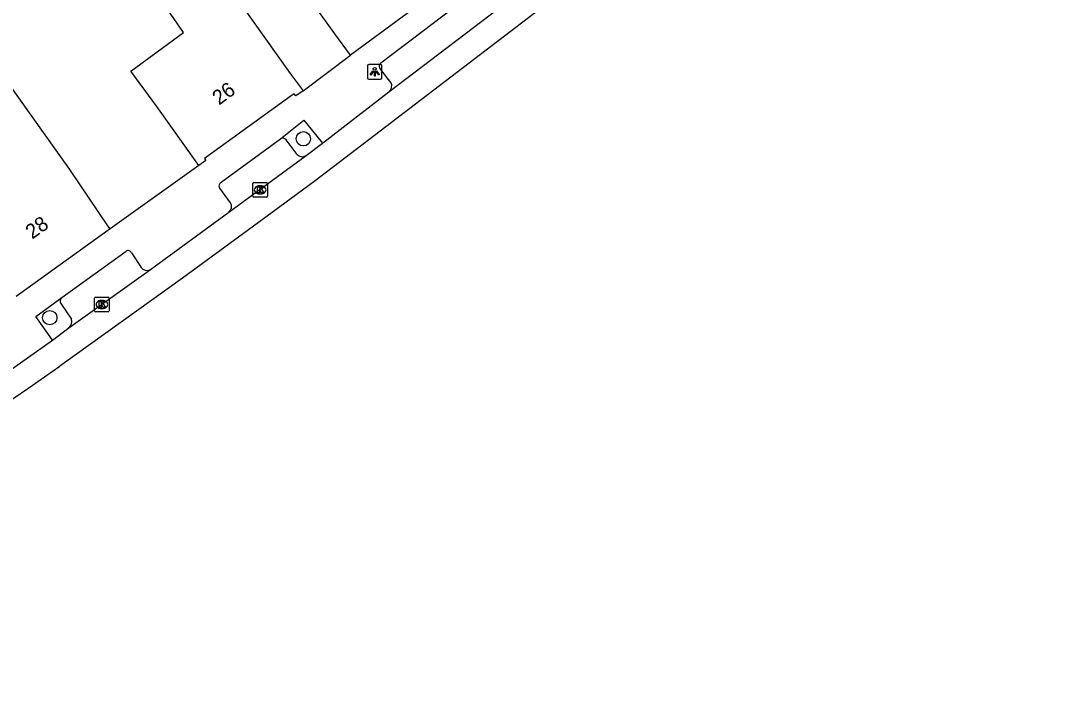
# Model space of a CAD drawing. Extents: x 159377 to 159983, y 382996 to 383595.
# Drawn here: x 159877.4 to 159949, y 383190.3 to 383236.9 of the extents above; entities that cross this region are included whole.
import ezdxf

# ---------------------------------------------------------------- set-up
doc = ezdxf.new("R2010")
doc.units = 0
for name, color, linetype in [('IMGEO_Boom', 7, 'Continuous'), ('IMGEO_Kolk', 7, 'Continuous'), ('IMGEO_Lichtpunt', 7, 'Continuous'), ('IMGEO_Pand', 7, 'Continuous'), ('IMGEO_Pand_nummerreeks', 7, 'Continuous'), ('IMGEO_Parkeervlak_open', 7, 'Continuous'), ('IMGEO_Rijbaan_lokaal_gesloten', 7, 'Continuous'), ('IMGEO_Voetpad_open', 7, 'Continuous')]:
    doc.layers.add(name, color=color, linetype=linetype)

msp = doc.modelspace()

# ---------------------------------------------------------------- linework, layer by layer
at = {"layer": 'IMGEO_Boom'}
for centre in [(159896.695, 383228.822), (159879.406, 383216.62)]:
    msp.add_circle(centre, 0.489, dxfattribs=at)
at = {"layer": 'IMGEO_Kolk'}
for p, q in [((159893.249, 383224.914), (159893.249, 383225.766)), ((159893.324, 383225.84), (159894.176, 383225.84)), ((159894.25, 383225.766), (159894.25, 383224.914)), ((159893.76, 383225.06), (159893.735, 383225.06)), ((159893.737, 383225.62), (159893.762, 383225.62)), ((159894.176, 383224.84), (159893.324, 383224.84)), ((159882.46, 383217.094), (159882.46, 383217.946)), ((159882.535, 383218.02), (159883.387, 383218.02)), ((159883.461, 383217.946), (159883.461, 383217.094)), ((159882.971, 383217.24), (159882.946, 383217.24)), ((159882.948, 383217.8), (159882.973, 383217.8)), ((159883.387, 383217.02), (159882.535, 383217.02))]:
    msp.add_line(p, q, dxfattribs=at)
for points in [[(159893.249, 383224.914), (159893.249, 383225.766)], [(159893.324, 383225.84), (159894.176, 383225.84)], [(159894.25, 383225.766), (159894.25, 383224.914)], [(159893.57, 383225.54), (159893.693, 383225.54), (159893.693, 383225.389), (159893.823, 383225.54), (159893.987, 383225.54), (159893.841, 383225.389), (159893.994, 383225.14), (159893.842, 383225.14), (159893.757, 383225.304), (159893.693, 383225.237), (159893.693, 383225.14), (159893.57, 383225.14), (159893.57, 383225.54)], [(159894.176, 383224.84), (159893.324, 383224.84)], [(159882.46, 383217.094), (159882.46, 383217.946)], [(159882.535, 383218.02), (159883.387, 383218.02)], [(159883.461, 383217.946), (159883.461, 383217.094)], [(159882.781, 383217.72), (159882.904, 383217.72), (159882.904, 383217.569), (159883.034, 383217.72), (159883.198, 383217.72), (159883.052, 383217.569), (159883.205, 383217.32), (159883.053, 383217.32), (159882.968, 383217.484), (159882.904, 383217.417), (159882.904, 383217.32), (159882.781, 383217.32), (159882.781, 383217.72)], [(159883.387, 383217.02), (159882.535, 383217.02)]]:
    msp.add_lwpolyline(points, dxfattribs=at)
for centre, start, end in [((159893.326, 383225.764), 91.55205, 178.44795), ((159893.326, 383225.764), 91.55205, 178.44795), ((159894.174, 383225.764), 1.55205, 88.44795), ((159894.174, 383225.764), 1.55205, 88.44795), ((159893.326, 383224.916), 181.55205, 268.44795), ((159893.326, 383224.916), 181.55205, 268.44795), ((159894.174, 383224.916), 271.55205, 358.44795), ((159894.174, 383224.916), 271.55205, 358.44795), ((159882.537, 383217.944), 91.55205, 178.44795), ((159882.537, 383217.944), 91.55205, 178.44795), ((159883.385, 383217.944), 1.55205, 88.44795), ((159883.385, 383217.944), 1.55205, 88.44795), ((159882.537, 383217.096), 181.55205, 268.44795), ((159882.537, 383217.096), 181.55205, 268.44795), ((159883.385, 383217.096), 271.55205, 358.44795), ((159883.385, 383217.096), 271.55205, 358.44795)]:
    msp.add_arc(centre, 0.0765, start, end, dxfattribs=at)
for centre, major_axis, ratio, start_param, end_param in [((159893.736, 383225.34), (-0.387, 0.002), 0.722429, 4.712389, 7.853982), ((159893.761, 383225.34), (-0.39, 0.002), 0.717154, 1.570796, 4.712389), ((159882.947, 383217.52), (-0.387, 0.002), 0.722429, 4.712389, 7.853982), ((159882.972, 383217.52), (-0.39, 0.002), 0.717154, 1.570796, 4.712389)]:
    msp.add_ellipse(centre, major_axis=major_axis, ratio=ratio, start_param=start_param, end_param=end_param, dxfattribs=at)
at = {"layer": 'IMGEO_Lichtpunt'}
for p, q in [((159901.057, 383233.794), (159901.057, 383232.987)), ((159901.057, 383233.794), (159901.057, 383232.987)), ((159901.959, 383233.889), (159901.151, 383233.889)), ((159901.959, 383233.889), (159901.151, 383233.889)), ((159902.053, 383232.987), (159902.053, 383233.794)), ((159902.053, 383232.987), (159902.053, 383233.794)), ((159901.151, 383232.893), (159901.959, 383232.893)), ((159901.151, 383232.893), (159901.959, 383232.893))]:
    msp.add_line(p, q, dxfattribs=at)
for points in [[(159901.431, 383233.458), (159901.47, 383233.43), (159901.282, 383233.168), (159901.244, 383233.195), (159901.431, 383233.458)], [(159901.533, 383233.41), (159901.58, 383233.41), (159901.58, 383233.088), (159901.533, 383233.088), (159901.533, 383233.41)], [(159901.643, 383233.43), (159901.681, 383233.457), (159901.868, 383233.195), (159901.829, 383233.167), (159901.643, 383233.43)]]:
    msp.add_lwpolyline(points, dxfattribs=at)
msp.add_circle((159901.556, 383233.592), 0.0994, dxfattribs=at)
for centre, start, end in [((159901.151, 383233.794), 90, 180), ((159901.151, 383233.794), 90, 180), ((159901.959, 383233.794), 0, 90), ((159901.959, 383233.794), 0, 90), ((159901.151, 383232.987), 180, 270), ((159901.151, 383232.987), 180, 270), ((159901.959, 383232.987), 270, 0), ((159901.959, 383232.987), 270, 360)]:
    msp.add_arc(centre, 0.0946, start, end, dxfattribs=at)
at = {"layer": 'IMGEO_Pand'}
for points in [[(159889.569, 383226.993), (159886.701, 383231.03), (159884.934, 383233.432), (159888.517, 383236.07), (159883.921, 383242.774), (159883.447, 383242.45), (159880.783, 383246.335), (159878.465, 383249.715), (159882.326, 383252.361), (159884.643, 383248.981)], [(159884.643, 383248.981), (159895.805, 383233.284), (159896.67, 383232.088)], [(159899.898, 383234.52), (159898.839, 383235.976), (159891.454, 383246.285)], [(159906.181, 383239.17), (159899.898, 383234.52)], [(159883.516, 383222.686), (159883.37, 383222.888), (159880.771, 383226.738), (159878.98, 383229.251), (159874.49, 383235.552), (159870.877, 383232.977), (159876.562, 383227.528), (159875.367, 383226.676), (159872.459, 383224.604)], [(159896.67, 383232.088), (159896.175, 383231.743), (159896.057, 383231.892), (159895.862, 383231.751), (159889.944, 383227.479), (159890.046, 383227.35), (159889.569, 383226.993)], [(159883.516, 383222.686), (159877.122, 383218.059)]]:
    msp.add_lwpolyline(points, dxfattribs=at)
at = {"layer": 'IMGEO_Parkeervlak_open'}
for points in [[(159896.278, 383227.758), (159895.515, 383228.758)], [(159880.164, 383217.597), (159880.891, 383216.526)]]:
    msp.add_lwpolyline(points, dxfattribs=at)
for centre, radius, start, end in [((159895.291, 383228.579), 0.287, 38.58215, 125.03394), ((159896.625, 383228.045), 0.45, 219.54604, 304.14028), ((159880.419, 383217.758), 0.301, 128.339, 212.22187), ((159880.38, 383216.36), 0.537, 308.15447, 17.98275)]:
    msp.add_arc(centre, radius, start, end, dxfattribs=at)
at = {"layer": 'IMGEO_Rijbaan_lokaal_gesloten'}
for points in [[(159949.02, 383265.371), (159897.491, 383225.958), (159894.22, 383223.535), (159888.449, 383219.325), (159880.097, 383213.321)], [(159902.531, 383232.027), (159911.142, 383238.598), (159917.448, 383243.448)], [(159896.67, 383232.088), (159899.898, 383234.52)], [(159898.003, 383228.514), (159902.531, 383232.027)], [(159896.878, 383227.672), (159898.003, 383228.514)], [(159891.624, 383223.825), (159896.878, 383227.672)], [(159886.266, 383219.897), (159891.624, 383223.825)], [(159880.712, 383215.938), (159886.266, 383219.897)], [(159879.592, 383215.083), (159880.712, 383215.938)], [(159875.367, 383212.109), (159879.592, 383215.083)]]:
    msp.add_lwpolyline(points, dxfattribs=at)
msp.add_arc((159202.186, 384183.711), 1183.732, 302.940386, 304.938016, dxfattribs=at)
at = {"layer": 'IMGEO_Voetpad_open'}
for points in [[(159901.983, 383233.992), (159909.025, 383239.354), (159915.741, 383244.492)], [(159902.663, 383232.656), (159901.942, 383233.576)], [(159895.126, 383228.814), (159896.721, 383230.096), (159898.003, 383228.514)], [(159891.083, 383225.86), (159895.126, 383228.814)], [(159889.569, 383226.993), (159883.516, 383222.686)], [(159891.73, 383224.449), (159890.989, 383225.445)], [(159880.232, 383217.994), (159884.616, 383221.163)], [(159884.976, 383221.046), (159885.628, 383220.043)], [(159879.592, 383215.083), (159878.461, 383216.704), (159880.232, 383217.994)]]:
    msp.add_lwpolyline(points, dxfattribs=at)
for centre, radius, start, end in [((159902.147, 383233.766), 0.279, 125.97116, 222.77132), ((159902.216, 383232.422), 0.505, 308.63516, 27.66099), ((159891.243, 383225.606), 0.301, 122.21154, 212.26348), ((159891.323, 383224.197), 0.478, 308.92772, 31.79046), ((159884.747, 383220.955), 0.246, 21.77169, 122.21999), ((159886.035, 383220.354), 0.512, 217.41437, 296.80636)]:
    msp.add_arc(centre, radius, start, end, dxfattribs=at)

# ---------------------------------------------------------------- texts
at = {"layer": 'IMGEO_Pand_nummerreeks'}
for s, rotation, p in [('26', 36.35417, (159890.951, 383231.079)), ('28', 35.50046, (159878.209, 383221.94))]:
    msp.add_text(s, height=1, rotation=rotation, dxfattribs=at).set_placement(p)

doc.saveas('drawing.dxf')
